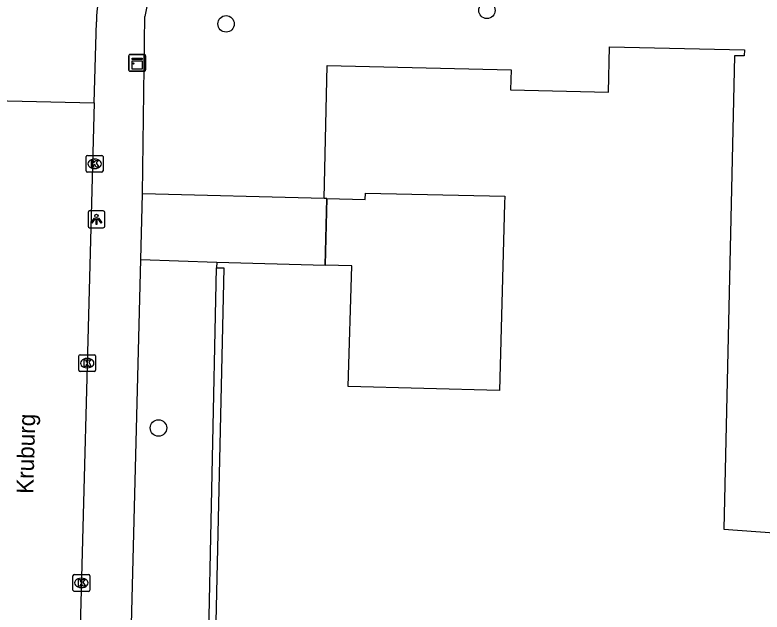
# Model space of a CAD drawing. Extents: x 162082 to 163393, y 388091 to 388632.
# Drawn here: x 162489.83 to 162534.22, y 388152.9 to 388188.35 of the extents above; entities that cross this region are included whole.
import ezdxf

# ---------------------------------------------------------------- set-up
doc = ezdxf.new("R2010")
doc.units = 0
for name, color, linetype in [('IMGEO_Boom', 7, 'Continuous'), ('IMGEO_Groenvoorziening', 7, 'Continuous'), ('IMGEO_Hek', 7, 'Continuous'), ('IMGEO_Kast', 7, 'Continuous'), ('IMGEO_Kolk', 7, 'Continuous'), ('IMGEO_Lichtpunt', 7, 'Continuous'), ('IMGEO_Openbare_ruimte_label', 7, 'Continuous'), ('IMGEO_Pand', 7, 'Continuous'), ('IMGEO_Rijbaan_lokaal_open', 7, 'Continuous'), ('IMGEO_Voetpad_open', 7, 'Continuous')]:
    doc.layers.add(name, color=color, linetype=linetype)

msp = doc.modelspace()

# ---------------------------------------------------------------- linework, layer by layer
at = {"layer": 'IMGEO_Boom'}
for centre in [(162517.872, 388188.623), (162502.375, 388187.822), (162498.36, 388163.828)]:
    msp.add_circle(centre, 0.489, dxfattribs=at)
at = {"layer": 'IMGEO_Groenvoorziening'}
msp.add_lwpolyline([(162496.672, 388149.058), (162500, 388148.917), (162501.289, 388148.862), (162501.808, 388173.337)], dxfattribs=at)
at = {"layer": 'IMGEO_Hek'}
msp.add_lwpolyline([(162508.354, 388177.449), (162508.255, 388173.491)], dxfattribs=at)
at = {"layer": 'IMGEO_Kast'}
for p, q in [((162496.594, 388185.079), (162496.594, 388185.92)), ((162496.594, 388185.92), (162496.594, 388185.079)), ((162496.669, 388186.004), (162497.51, 388186.004)), ((162497.51, 388186.004), (162496.669, 388186.004)), ((162497.594, 388185.929), (162497.594, 388185.088)), ((162497.594, 388185.088), (162497.594, 388185.929)), ((162497.519, 388185.004), (162496.678, 388185.004)), ((162496.678, 388185.004), (162497.519, 388185.004))]:
    msp.add_line(p, q, dxfattribs=at)
for points in [[(162496.789, 388185.794), (162497.389, 388185.794), (162497.389, 388185.709), (162496.789, 388185.709), (162496.789, 388185.794)], [(162496.789, 388185.619), (162497.389, 388185.619), (162497.389, 388185.13), (162496.789, 388185.13), (162496.789, 388185.619)]]:
    msp.add_lwpolyline(points, dxfattribs=at)
msp.add_circle((162496.873, 388185.468), 0.0377, dxfattribs=at)
for centre, start, end in [((162496.672, 388185.926), 92.4484, 184.2845), ((162496.672, 388185.926), 92.4484, 184.2845), ((162497.516, 388185.926), 2.4484, 94.2845), ((162497.516, 388185.926), 2.4484, 94.2845), ((162496.672, 388185.082), 182.4484, 274.2845), ((162496.672, 388185.082), 182.4484, 274.2845), ((162497.516, 388185.082), 272.4484, 4.2845), ((162497.516, 388185.082), 272.4484, 4.2845)]:
    msp.add_arc(centre, 0.0779, start, end, dxfattribs=at)
at = {"layer": 'IMGEO_Kolk'}
for p, q in [((162494.139, 388180.012), (162494.991, 388180.012)), ((162494.064, 388179.086), (162494.064, 388179.938)), ((162494.552, 388179.792), (162494.577, 388179.792)), ((162495.065, 388179.938), (162495.065, 388179.086)), ((162494.575, 388179.232), (162494.55, 388179.232)), ((162494.991, 388179.012), (162494.139, 388179.012)), ((162493.625, 388167.253), (162493.625, 388168.105)), ((162493.7, 388168.179), (162494.552, 388168.179)), ((162494.626, 388168.105), (162494.626, 388167.253)), ((162494.113, 388167.959), (162494.138, 388167.959)), ((162494.552, 388167.179), (162493.7, 388167.179)), ((162494.136, 388167.399), (162494.111, 388167.399)), ((162493.354, 388155.126), (162494.206, 388155.126)), ((162493.279, 388154.2), (162493.279, 388155.052)), ((162493.767, 388154.906), (162493.792, 388154.906)), ((162494.28, 388155.052), (162494.28, 388154.2)), ((162493.79, 388154.346), (162493.765, 388154.346)), ((162494.206, 388154.126), (162493.354, 388154.126))]:
    msp.add_line(p, q, dxfattribs=at)
for points in [[(162494.139, 388180.012), (162494.991, 388180.012)], [(162494.064, 388179.086), (162494.064, 388179.938)], [(162494.385, 388179.712), (162494.508, 388179.712), (162494.508, 388179.561), (162494.638, 388179.712), (162494.802, 388179.712), (162494.656, 388179.561), (162494.809, 388179.312), (162494.657, 388179.312), (162494.572, 388179.476), (162494.508, 388179.409), (162494.508, 388179.312), (162494.385, 388179.312), (162494.385, 388179.712)], [(162495.065, 388179.938), (162495.065, 388179.086)], [(162494.991, 388179.012), (162494.139, 388179.012)], [(162493.625, 388167.253), (162493.625, 388168.105)], [(162493.7, 388168.179), (162494.552, 388168.179)], [(162494.626, 388168.105), (162494.626, 388167.253)], [(162493.946, 388167.879), (162494.069, 388167.879), (162494.069, 388167.728), (162494.199, 388167.879), (162494.363, 388167.879), (162494.217, 388167.728), (162494.37, 388167.479), (162494.218, 388167.479), (162494.133, 388167.643), (162494.069, 388167.576), (162494.069, 388167.479), (162493.946, 388167.479), (162493.946, 388167.879)], [(162494.552, 388167.179), (162493.7, 388167.179)], [(162493.354, 388155.126), (162494.206, 388155.126)], [(162493.279, 388154.2), (162493.279, 388155.052)], [(162493.6, 388154.826), (162493.723, 388154.826), (162493.723, 388154.675), (162493.853, 388154.826), (162494.017, 388154.826), (162493.871, 388154.675), (162494.024, 388154.426), (162493.872, 388154.426), (162493.787, 388154.59), (162493.723, 388154.523), (162493.723, 388154.426), (162493.6, 388154.426), (162493.6, 388154.826)], [(162494.28, 388155.052), (162494.28, 388154.2)], [(162494.206, 388154.126), (162493.354, 388154.126)]]:
    msp.add_lwpolyline(points, dxfattribs=at)
for centre, start, end in [((162494.141, 388179.936), 91.552, 178.448), ((162494.141, 388179.936), 91.552, 178.448), ((162494.989, 388179.936), 1.552, 88.448), ((162494.989, 388179.936), 1.552, 88.448), ((162494.141, 388179.088), 181.552, 268.448), ((162494.141, 388179.088), 181.552, 268.448), ((162494.989, 388179.088), 271.552, 358.448), ((162494.989, 388179.088), 271.552, 358.448), ((162493.702, 388168.103), 91.552, 178.448), ((162493.702, 388168.103), 91.552, 178.448), ((162494.55, 388168.103), 1.552, 88.448), ((162494.55, 388168.103), 1.552, 88.448), ((162493.702, 388167.255), 181.552, 268.448), ((162493.702, 388167.255), 181.552, 268.448), ((162494.55, 388167.255), 271.552, 358.448), ((162494.55, 388167.255), 271.552, 358.448), ((162493.356, 388155.05), 91.552, 178.448), ((162493.356, 388155.05), 91.552, 178.448), ((162494.204, 388155.05), 1.552, 88.448), ((162494.204, 388155.05), 1.552, 88.448), ((162493.356, 388154.202), 181.552, 268.448), ((162493.356, 388154.202), 181.552, 268.448), ((162494.204, 388154.202), 271.552, 358.448), ((162494.204, 388154.202), 271.552, 358.448)]:
    msp.add_arc(centre, 0.0765, start, end, dxfattribs=at)
for centre, major_axis, ratio, start_param, end_param in [((162494.551, 388179.512), (-0.387, 0.002), 0.722429, 4.712389, 7.853982), ((162494.576, 388179.512), (-0.39, 0.002), 0.717154, 1.570796, 4.712389), ((162494.112, 388167.679), (-0.387, 0.002), 0.722429, 4.712389, 7.853982), ((162494.137, 388167.679), (-0.39, 0.002), 0.717154, 1.570796, 4.712389), ((162493.766, 388154.626), (-0.387, 0.002), 0.722429, 4.712389, 7.853982), ((162493.791, 388154.626), (-0.39, 0.002), 0.717154, 1.570796, 4.712389)]:
    msp.add_ellipse(centre, major_axis=major_axis, ratio=ratio, start_param=start_param, end_param=end_param, dxfattribs=at)
at = {"layer": 'IMGEO_Lichtpunt'}
for p, q in [((162494.176, 388176.62), (162494.176, 388175.813)), ((162494.176, 388176.62), (162494.176, 388175.813)), ((162495.078, 388176.715), (162494.27, 388176.715)), ((162495.078, 388176.715), (162494.27, 388176.715)), ((162495.172, 388175.813), (162495.172, 388176.62)), ((162495.172, 388175.813), (162495.172, 388176.62)), ((162494.27, 388175.719), (162495.078, 388175.719)), ((162494.27, 388175.719), (162495.078, 388175.719))]:
    msp.add_line(p, q, dxfattribs=at)
for points in [[(162494.55, 388176.284), (162494.589, 388176.256), (162494.401, 388175.994), (162494.363, 388176.021), (162494.55, 388176.284)], [(162494.652, 388176.236), (162494.699, 388176.236), (162494.699, 388175.914), (162494.652, 388175.914), (162494.652, 388176.236)], [(162494.762, 388176.256), (162494.8, 388176.283), (162494.987, 388176.021), (162494.948, 388175.993), (162494.762, 388176.256)]]:
    msp.add_lwpolyline(points, dxfattribs=at)
msp.add_circle((162494.675, 388176.418), 0.0994, dxfattribs=at)
for centre, start, end in [((162494.27, 388176.62), 90, 180), ((162494.27, 388176.62), 90, 180), ((162495.078, 388176.62), 0, 90), ((162495.078, 388176.62), 0, 90), ((162494.27, 388175.813), 180, 270), ((162494.27, 388175.813), 180, 270), ((162495.078, 388175.813), 270, 0), ((162495.078, 388175.813), 270, 360)]:
    msp.add_arc(centre, 0.0946, start, end, dxfattribs=at)
at = {"layer": 'IMGEO_Pand'}
for points in [[(162508.198, 388177.453), (162508.378, 388185.349), (162519.306, 388185.1), (162519.279, 388183.908), (162525.093, 388183.776), (162525.155, 388186.463), (162533.167, 388186.281), (162533.159, 388185.915), (162532.576, 388185.928), (162531.936, 388157.81), (162536.032, 388157.53)], [(162508.354, 388177.449), (162510.644, 388177.397), (162510.653, 388177.772), (162518.928, 388177.584), (162518.918, 388177.148), (162518.617, 388166.048), (162509.62, 388166.292), (162509.839, 388173.445), (162508.255, 388173.491)], [(162508.354, 388177.449), (162508.198, 388177.453)], [(162501.808, 388173.337), (162502.242, 388173.327), (162501.665, 388147.913), (162501.289, 388147.921), (162501.281, 388147.559), (162508.944, 388147.385)], [(162501.817, 388173.679), (162501.808, 388173.337)], [(162501.817, 388173.679), (162508.255, 388173.491)]]:
    msp.add_lwpolyline(points, dxfattribs=at)
at = {"layer": 'IMGEO_Rijbaan_lokaal_open'}
for points in [[(162494.536, 388183.135), (162494.684, 388187.95)], [(162488.529, 388183.267), (162494.536, 388183.135)], [(162494.536, 388183.135), (162493.484, 388143.829)]]:
    msp.add_lwpolyline(points, dxfattribs=at)
msp.add_arc((162500.626, 388188.052), 5.943, 134.8061, 180.9792, dxfattribs=at)
at = {"layer": 'IMGEO_Voetpad_open'}
for points in [[(162497.407, 388177.721), (162497.558, 388188.258)], [(162497.308, 388173.837), (162497.407, 388177.721)], [(162508.198, 388177.453), (162497.407, 388177.721)], [(162508.255, 388173.491), (162508.354, 388177.449)], [(162496.672, 388149.058), (162497.308, 388173.837)], [(162497.308, 388173.837), (162499.55, 388173.758), (162501.817, 388173.679)]]:
    msp.add_lwpolyline(points, dxfattribs=at)
msp.add_arc((162501.682, 388187.838), 4.145, 87.5092, 174.1806, dxfattribs=at)

# ---------------------------------------------------------------- texts
at = {"layer": 'IMGEO_Openbare_ruimte_label'}
msp.add_text('Kruburg', height=1, rotation=88.5106, dxfattribs=at).set_placement((162490.922, 388159.905))

doc.saveas('drawing.dxf')
